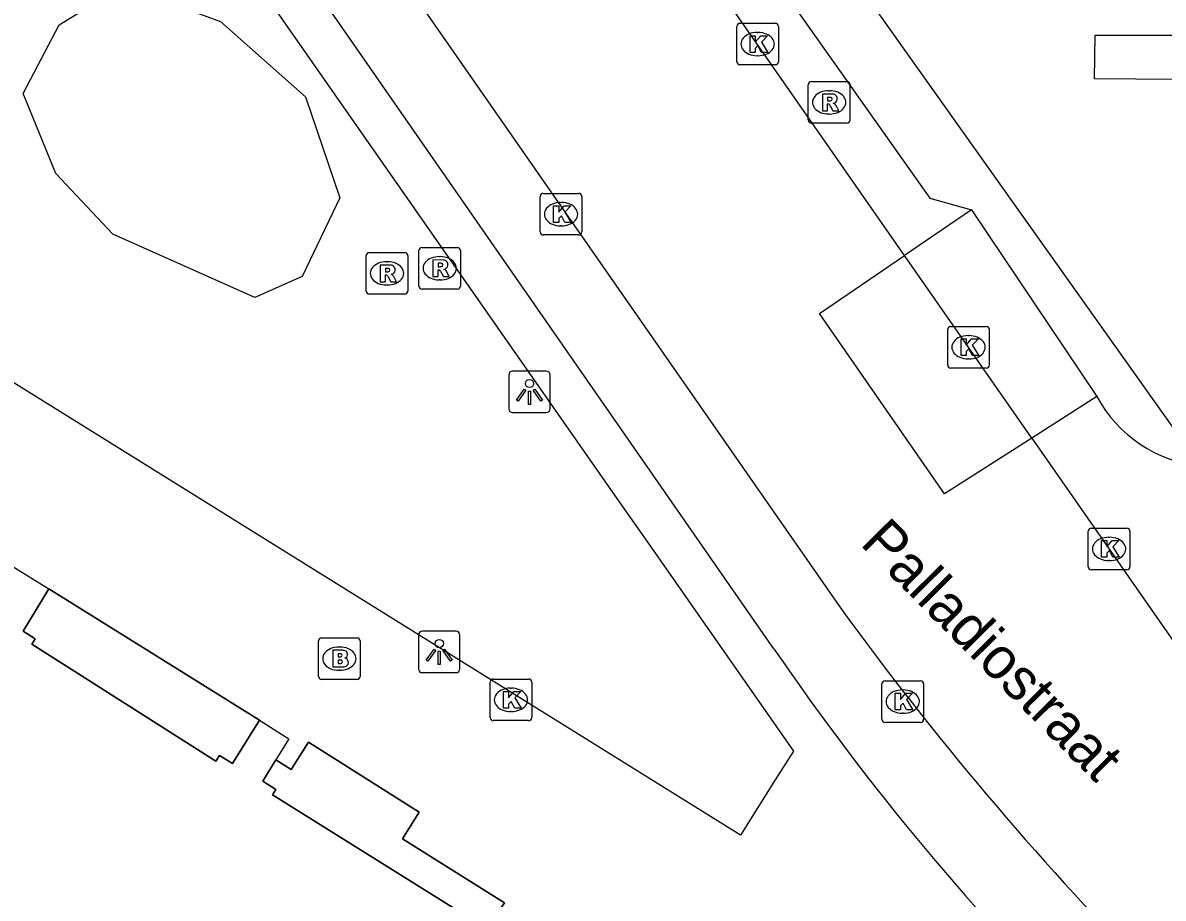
# Model space of a CAD drawing. Extents: x 159353 to 160616, y 385893 to 387321.
# Drawn here: x 159922.1 to 159949.51, y 386152.95 to 386173.99 of the extents above; entities that cross this region are included whole.
import ezdxf

# ---------------------------------------------------------------- set-up
doc = ezdxf.new("R2010")
doc.units = 0
for name, color, linetype in [('IMGEO_Brandkraan', 7, 'Continuous'), ('IMGEO_Groenvoorziening', 7, 'Continuous'), ('IMGEO_Kolk', 7, 'Continuous'), ('IMGEO_Lichtpunt', 7, 'Continuous'), ('IMGEO_Muur', 7, 'Continuous'), ('IMGEO_Openbare_ruimte_label', 7, 'Continuous'), ('IMGEO_Pand', 7, 'Continuous'), ('IMGEO_Pand_overbouw', 7, 'Continuous'), ('IMGEO_Rijbaan_lokaal_open', 7, 'Continuous'), ('IMGEO_Rioolput', 7, 'Continuous'), ('IMGEO_Voetpad_open', 7, 'Continuous')]:
    doc.layers.add(name, color=color, linetype=linetype)

msp = doc.modelspace()

# ---------------------------------------------------------------- linework, layer by layer
at = {"layer": 'IMGEO_Brandkraan'}
for p, q in [((159929.212, 386158.285), (159929.212, 386159.137)), ((159929.287, 386159.211), (159930.139, 386159.211)), ((159930.213, 386159.137), (159930.213, 386158.285)), ((159929.7, 386158.991), (159929.725, 386158.991)), ((159930.139, 386158.211), (159929.287, 386158.211)), ((159929.723, 386158.431), (159929.698, 386158.431))]:
    msp.add_line(p, q, dxfattribs=at)
for points in [[(159929.212, 386158.285), (159929.212, 386159.137)], [(159929.287, 386159.211), (159930.139, 386159.211)], [(159930.213, 386159.137), (159930.213, 386158.285)], [(159929.56, 386158.911), (159929.56, 386158.511), (159929.773, 386158.511)], [(159929.791, 386158.911), (159929.56, 386158.911)], [(159929.739, 386158.83), (159929.685, 386158.83), (159929.685, 386158.754)], [(159929.685, 386158.754), (159929.738, 386158.754)], [(159929.747, 386158.678), (159929.685, 386158.678), (159929.685, 386158.597)], [(159929.685, 386158.597), (159929.747, 386158.597)], [(159930.139, 386158.211), (159929.287, 386158.211)]]:
    msp.add_lwpolyline(points, dxfattribs=at)
for centre, radius, start, end in [((159929.289, 386159.135), 0.0765, 91.552, 178.448), ((159929.289, 386159.135), 0.0765, 91.552, 178.448), ((159930.137, 386159.135), 0.0765, 1.552, 88.448), ((159930.137, 386159.135), 0.0765, 1.552, 88.448), ((159929.74, 386158.792), 0.0379, 267.8285, 90.9355), ((159929.795, 386158.766), 0.145, 59.4692, 91.5367), ((159929.82, 386158.813), 0.0922, 285.5137, 58.1501), ((159929.748, 386158.637), 0.0404, 269.8759, 90.5077), ((159929.779, 386158.762), 0.251, 268.6676, 293.5347), ((159929.825, 386158.621), 0.105, 301.3115, 78.989), ((159929.289, 386158.287), 0.0765, 181.552, 268.448), ((159929.289, 386158.287), 0.0765, 181.552, 268.448), ((159930.137, 386158.287), 0.0765, 271.552, 358.448), ((159930.137, 386158.287), 0.0765, 271.552, 358.448)]:
    msp.add_arc(centre, radius, start, end, dxfattribs=at)
for centre, major_axis, ratio, start_param, end_param in [((159929.699, 386158.711), (-0.387, 0.002), 0.722429, 4.712389, 7.853982), ((159929.724, 386158.711), (-0.39, 0.002), 0.717154, 1.570796, 4.712389)]:
    msp.add_ellipse(centre, major_axis=major_axis, ratio=ratio, start_param=start_param, end_param=end_param, dxfattribs=at)
at = {"layer": 'IMGEO_Groenvoorziening'}
msp.add_lwpolyline([(159927.684, 386167.388), (159924.272, 386168.908), (159922.898, 386170.37), (159922.113, 386172.293), (159922.976, 386173.942), (159924.506, 386174.884), (159926.86, 386174.02), (159928.9, 386172.215), (159929.724, 386169.782), (159928.821, 386167.898), (159927.684, 386167.388)], dxfattribs=at)
at = {"layer": 'IMGEO_Kolk'}
for p, q in [((159939.265, 386173.054), (159939.265, 386173.906)), ((159939.34, 386173.98), (159940.192, 386173.98)), ((159940.266, 386173.906), (159940.266, 386173.054)), ((159939.753, 386173.76), (159939.778, 386173.76)), ((159940.192, 386172.98), (159939.34, 386172.98)), ((159939.776, 386173.2), (159939.751, 386173.2)), ((159934.54, 386168.966), (159934.54, 386169.818)), ((159934.615, 386169.892), (159935.467, 386169.892)), ((159935.541, 386169.818), (159935.541, 386168.966)), ((159935.028, 386169.672), (159935.053, 386169.672)), ((159935.467, 386168.892), (159934.615, 386168.892)), ((159935.051, 386169.112), (159935.026, 386169.112)), ((159944.408, 386166.694), (159945.26, 386166.694)), ((159944.333, 386165.768), (159944.333, 386166.62)), ((159944.821, 386166.474), (159944.846, 386166.474)), ((159945.334, 386166.62), (159945.334, 386165.768)), ((159944.844, 386165.914), (159944.819, 386165.914)), ((159945.26, 386165.694), (159944.408, 386165.694)), ((159947.712, 386160.921), (159947.712, 386161.773)), ((159947.787, 386161.847), (159948.639, 386161.847)), ((159948.713, 386161.773), (159948.713, 386160.921)), ((159948.2, 386161.627), (159948.225, 386161.627)), ((159948.223, 386161.067), (159948.198, 386161.067)), ((159948.639, 386160.847), (159947.787, 386160.847)), ((159933.41, 386158.221), (159934.262, 386158.221)), ((159942.828, 386158.179), (159943.68, 386158.179)), ((159933.335, 386157.295), (159933.335, 386158.147)), ((159933.823, 386158.001), (159933.848, 386158.001)), ((159934.336, 386158.147), (159934.336, 386157.295)), ((159942.753, 386157.253), (159942.753, 386158.105)), ((159943.241, 386157.959), (159943.266, 386157.959)), ((159943.754, 386158.105), (159943.754, 386157.253)), ((159933.846, 386157.441), (159933.821, 386157.441)), ((159943.264, 386157.399), (159943.239, 386157.399)), ((159934.262, 386157.221), (159933.41, 386157.221)), ((159943.68, 386157.179), (159942.828, 386157.179))]:
    msp.add_line(p, q, dxfattribs=at)
for points in [[(159939.265, 386173.054), (159939.265, 386173.906)], [(159939.34, 386173.98), (159940.192, 386173.98)], [(159940.266, 386173.906), (159940.266, 386173.054)], [(159939.586, 386173.68), (159939.709, 386173.68), (159939.709, 386173.529), (159939.839, 386173.68), (159940.003, 386173.68), (159939.857, 386173.529), (159940.01, 386173.28), (159939.858, 386173.28), (159939.773, 386173.444), (159939.709, 386173.377), (159939.709, 386173.28), (159939.586, 386173.28), (159939.586, 386173.68)], [(159940.192, 386172.98), (159939.34, 386172.98)], [(159934.54, 386168.966), (159934.54, 386169.818)], [(159934.615, 386169.892), (159935.467, 386169.892)], [(159935.541, 386169.818), (159935.541, 386168.966)], [(159934.861, 386169.592), (159934.984, 386169.592), (159934.984, 386169.441), (159935.114, 386169.592), (159935.278, 386169.592), (159935.132, 386169.441), (159935.285, 386169.192), (159935.133, 386169.192), (159935.048, 386169.356), (159934.984, 386169.289), (159934.984, 386169.192), (159934.861, 386169.192), (159934.861, 386169.592)], [(159935.467, 386168.892), (159934.615, 386168.892)], [(159944.408, 386166.694), (159945.26, 386166.694)], [(159944.333, 386165.768), (159944.333, 386166.62)], [(159945.334, 386166.62), (159945.334, 386165.768)], [(159944.654, 386166.394), (159944.777, 386166.394), (159944.777, 386166.243), (159944.907, 386166.394), (159945.071, 386166.394), (159944.925, 386166.243), (159945.078, 386165.994), (159944.926, 386165.994), (159944.841, 386166.158), (159944.777, 386166.091), (159944.777, 386165.994), (159944.654, 386165.994), (159944.654, 386166.394)], [(159945.26, 386165.694), (159944.408, 386165.694)], [(159947.712, 386160.921), (159947.712, 386161.773)], [(159947.787, 386161.847), (159948.639, 386161.847)], [(159948.713, 386161.773), (159948.713, 386160.921)], [(159948.033, 386161.547), (159948.156, 386161.547), (159948.156, 386161.396), (159948.286, 386161.547), (159948.45, 386161.547), (159948.304, 386161.396), (159948.457, 386161.147), (159948.305, 386161.147), (159948.22, 386161.311), (159948.156, 386161.244), (159948.156, 386161.147), (159948.033, 386161.147), (159948.033, 386161.547)], [(159948.639, 386160.847), (159947.787, 386160.847)], [(159933.41, 386158.221), (159934.262, 386158.221)], [(159942.828, 386158.179), (159943.68, 386158.179)], [(159933.335, 386157.295), (159933.335, 386158.147)], [(159933.656, 386157.921), (159933.779, 386157.921), (159933.779, 386157.77), (159933.909, 386157.921), (159934.073, 386157.921), (159933.927, 386157.77), (159934.08, 386157.521), (159933.928, 386157.521), (159933.843, 386157.685), (159933.779, 386157.618), (159933.779, 386157.521), (159933.656, 386157.521), (159933.656, 386157.921)], [(159934.336, 386158.147), (159934.336, 386157.295)], [(159942.753, 386157.253), (159942.753, 386158.105)], [(159943.754, 386158.105), (159943.754, 386157.253)], [(159943.074, 386157.879), (159943.197, 386157.879), (159943.197, 386157.728), (159943.327, 386157.879), (159943.491, 386157.879), (159943.345, 386157.728), (159943.498, 386157.479), (159943.346, 386157.479), (159943.261, 386157.643), (159943.197, 386157.576), (159943.197, 386157.479), (159943.074, 386157.479), (159943.074, 386157.879)], [(159934.262, 386157.221), (159933.41, 386157.221)], [(159943.68, 386157.179), (159942.828, 386157.179)]]:
    msp.add_lwpolyline(points, dxfattribs=at)
for centre, start, end in [((159939.342, 386173.904), 91.552, 178.448), ((159939.342, 386173.904), 91.552, 178.448), ((159940.19, 386173.904), 1.552, 88.448), ((159940.19, 386173.904), 1.552, 88.448), ((159939.342, 386173.056), 181.552, 268.448), ((159939.342, 386173.056), 181.552, 268.448), ((159940.19, 386173.056), 271.552, 358.448), ((159940.19, 386173.056), 271.552, 358.448), ((159934.617, 386169.816), 91.552, 178.448), ((159934.617, 386169.816), 91.552, 178.448), ((159935.465, 386169.816), 1.552, 88.448), ((159935.465, 386169.816), 1.552, 88.448), ((159934.617, 386168.968), 181.552, 268.448), ((159934.617, 386168.968), 181.552, 268.448), ((159935.465, 386168.968), 271.552, 358.448), ((159935.465, 386168.968), 271.552, 358.448), ((159944.41, 386166.618), 91.552, 178.448), ((159944.41, 386166.618), 91.552, 178.448), ((159945.258, 386166.618), 1.552, 88.448), ((159945.258, 386166.618), 1.552, 88.448), ((159944.41, 386165.77), 181.552, 268.448), ((159944.41, 386165.77), 181.552, 268.448), ((159945.258, 386165.77), 271.552, 358.448), ((159945.258, 386165.77), 271.552, 358.448), ((159947.789, 386161.771), 91.552, 178.448), ((159947.789, 386161.771), 91.552, 178.448), ((159948.637, 386161.771), 1.552, 88.448), ((159948.637, 386161.771), 1.552, 88.448), ((159947.789, 386160.923), 181.552, 268.448), ((159947.789, 386160.923), 181.552, 268.448), ((159948.637, 386160.923), 271.552, 358.448), ((159948.637, 386160.923), 271.552, 358.448), ((159933.412, 386158.145), 91.552, 178.448), ((159933.412, 386158.145), 91.552, 178.448), ((159934.26, 386158.145), 1.552, 88.448), ((159934.26, 386158.145), 1.552, 88.448), ((159942.83, 386158.103), 91.552, 178.448), ((159942.83, 386158.103), 91.552, 178.448), ((159943.678, 386158.103), 1.552, 88.448), ((159943.678, 386158.103), 1.552, 88.448), ((159933.412, 386157.297), 181.552, 268.448), ((159933.412, 386157.297), 181.552, 268.448), ((159934.26, 386157.297), 271.552, 358.448), ((159934.26, 386157.297), 271.552, 358.448), ((159942.83, 386157.255), 181.552, 268.448), ((159942.83, 386157.255), 181.552, 268.448), ((159943.678, 386157.255), 271.552, 358.448), ((159943.678, 386157.255), 271.552, 358.448)]:
    msp.add_arc(centre, 0.0765, start, end, dxfattribs=at)
for centre, major_axis, ratio, start_param, end_param in [((159939.752, 386173.48), (-0.387, 0.002), 0.722429, 4.712389, 7.853982), ((159939.777, 386173.48), (-0.39, 0.002), 0.717154, 1.570796, 4.712389), ((159935.027, 386169.392), (-0.387, 0.002), 0.722429, 4.712389, 7.853982), ((159935.052, 386169.392), (-0.39, 0.002), 0.717154, 1.570796, 4.712389), ((159944.82, 386166.194), (-0.387, 0.002), 0.722429, 4.712389, 7.853982), ((159944.845, 386166.194), (-0.39, 0.002), 0.717154, 1.570796, 4.712389), ((159948.199, 386161.347), (-0.387, 0.002), 0.722429, 4.712389, 7.853982), ((159948.224, 386161.347), (-0.39, 0.002), 0.717154, 1.570796, 4.712389), ((159933.822, 386157.721), (-0.387, 0.002), 0.722429, 4.712389, 7.853982), ((159933.847, 386157.721), (-0.39, 0.002), 0.717154, 1.570796, 4.712389), ((159943.24, 386157.679), (-0.387, 0.002), 0.722429, 4.712389, 7.853982), ((159943.265, 386157.679), (-0.39, 0.002), 0.717154, 1.570796, 4.712389)]:
    msp.add_ellipse(centre, major_axis=major_axis, ratio=ratio, start_param=start_param, end_param=end_param, dxfattribs=at)
at = {"layer": 'IMGEO_Lichtpunt'}
for p, q in [((159934.686, 386165.62), (159933.878, 386165.62)), ((159934.686, 386165.62), (159933.878, 386165.62)), ((159933.784, 386165.525), (159933.784, 386164.718)), ((159933.784, 386165.525), (159933.784, 386164.718)), ((159934.78, 386164.718), (159934.78, 386165.525)), ((159934.78, 386164.718), (159934.78, 386165.525)), ((159933.878, 386164.624), (159934.686, 386164.624)), ((159933.878, 386164.624), (159934.686, 386164.624)), ((159931.615, 386159.276), (159931.615, 386158.469)), ((159931.615, 386159.276), (159931.615, 386158.469)), ((159932.517, 386159.371), (159931.709, 386159.371)), ((159932.517, 386159.371), (159931.709, 386159.371)), ((159932.611, 386158.469), (159932.611, 386159.276)), ((159932.611, 386158.469), (159932.611, 386159.276)), ((159931.709, 386158.375), (159932.517, 386158.375)), ((159931.709, 386158.375), (159932.517, 386158.375))]:
    msp.add_line(p, q, dxfattribs=at)
for points in [[(159934.158, 386165.189), (159934.197, 386165.161), (159934.009, 386164.899), (159933.971, 386164.926), (159934.158, 386165.189)], [(159934.26, 386165.141), (159934.307, 386165.141), (159934.307, 386164.819), (159934.26, 386164.819), (159934.26, 386165.141)], [(159934.37, 386165.161), (159934.408, 386165.188), (159934.595, 386164.926), (159934.556, 386164.898), (159934.37, 386165.161)], [(159931.989, 386158.94), (159932.028, 386158.912), (159931.84, 386158.65), (159931.802, 386158.677), (159931.989, 386158.94)], [(159932.091, 386158.892), (159932.138, 386158.892), (159932.138, 386158.57), (159932.091, 386158.57), (159932.091, 386158.892)], [(159932.201, 386158.912), (159932.239, 386158.939), (159932.426, 386158.677), (159932.387, 386158.649), (159932.201, 386158.912)]]:
    msp.add_lwpolyline(points, dxfattribs=at)
for centre in [(159934.283, 386165.323), (159932.114, 386159.074)]:
    msp.add_circle(centre, 0.0994, dxfattribs=at)
for centre, start, end in [((159933.878, 386165.525), 90, 180), ((159933.878, 386165.525), 90, 180), ((159934.686, 386165.525), 0, 90), ((159934.686, 386165.525), 0, 90), ((159933.878, 386164.718), 180, 270), ((159933.878, 386164.718), 180, 270), ((159934.686, 386164.718), 270, 0), ((159934.686, 386164.718), 270, 360), ((159931.709, 386159.276), 90, 180), ((159931.709, 386159.276), 90, 180), ((159932.517, 386159.276), 0, 90), ((159932.517, 386159.276), 0, 90), ((159931.709, 386158.469), 180, 270), ((159931.709, 386158.469), 180, 270), ((159932.517, 386158.469), 270, 0), ((159932.517, 386158.469), 270, 360)]:
    msp.add_arc(centre, 0.0946, start, end, dxfattribs=at)
at = {"layer": 'IMGEO_Muur'}
msp.add_lwpolyline([(159952.828, 386172.605), (159947.863, 386172.645), (159947.875, 386173.695), (159952.802, 386173.696), (159952.828, 386172.605)], dxfattribs=at)
at = {"layer": 'IMGEO_Pand'}
for points in [[(159916.885, 386153.064), (159921.823, 386160.953), (159922.729, 386160.385)], [(159927.792, 386157.236), (159927.145, 386156.194), (159926.834, 386156.387), (159926.746, 386156.251), (159922.32, 386159.055), (159922.403, 386159.191), (159922.112, 386159.368), (159922.729, 386160.385)], [(159927.792, 386157.236), (159928.5, 386156.783), (159928.183, 386156.277)], [(159933.682, 386152.845), (159933.344, 386152.351), (159932.942, 386152.602), (159932.851, 386152.471), (159928.106, 386155.436), (159928.184, 386155.567), (159927.87, 386155.768), (159928.183, 386156.277)]]:
    msp.add_lwpolyline(points, dxfattribs=at)
at = {"layer": 'IMGEO_Pand_overbouw'}
for points in [[(159927.792, 386157.236), (159922.729, 386160.385), (159922.112, 386159.368), (159922.403, 386159.191), (159922.32, 386159.055), (159926.746, 386156.251), (159926.834, 386156.387), (159927.145, 386156.194)], [(159931.631, 386155.022), (159928.971, 386156.705), (159928.555, 386156.044), (159928.183, 386156.277), (159927.87, 386155.768), (159928.184, 386155.567), (159928.106, 386155.436), (159932.851, 386152.471), (159932.942, 386152.602), (159933.344, 386152.351), (159933.682, 386152.845), (159931.229, 386154.378)]]:
    msp.add_lwpolyline(points, close=True, dxfattribs=at)
at = {"layer": 'IMGEO_Rijbaan_lokaal_open'}
for points in [[(159950.418, 386163.332), (159935.64, 386184.131)], [(159934.663, 386182.851), (159943.907, 386169.776), (159944.906, 386169.496)], [(159925.909, 386182.701), (159941.775, 386159.906)], [(159943.298, 386168.4), (159933.698, 386182.179)], [(159944.906, 386169.496), (159947.92, 386165.009)], [(159946.357, 386164.01), (159944.26, 386162.67), (159941.249, 386167.002), (159943.298, 386168.4)], [(159946.357, 386164.01), (159950.025, 386158.745)]]:
    msp.add_lwpolyline(points, dxfattribs=at)
for centre, radius, start, end in [((159950.774, 386166.561), 3.249, 208.5402, 263.7099), ((160004.269, 386205.287), 77.233, 215.98595, 224.40306)]:
    msp.add_arc(centre, radius, start, end, dxfattribs=at)
at = {"layer": 'IMGEO_Rioolput'}
for p, q in [((159940.984, 386171.653), (159940.984, 386172.505)), ((159941.059, 386172.579), (159941.911, 386172.579)), ((159941.985, 386172.505), (159941.985, 386171.653)), ((159941.472, 386172.359), (159941.497, 386172.359)), ((159941.495, 386171.799), (159941.47, 386171.799)), ((159941.911, 386171.579), (159941.059, 386171.579)), ((159931.7, 386168.592), (159932.552, 386168.592)), ((159930.357, 386167.544), (159930.357, 386168.396)), ((159930.432, 386168.47), (159931.284, 386168.47)), ((159931.358, 386168.396), (159931.358, 386167.544)), ((159931.625, 386167.666), (159931.625, 386168.518)), ((159932.113, 386168.372), (159932.138, 386168.372)), ((159932.626, 386168.518), (159932.626, 386167.666)), ((159930.845, 386168.25), (159930.87, 386168.25)), ((159932.136, 386167.812), (159932.111, 386167.812)), ((159930.868, 386167.69), (159930.843, 386167.69)), ((159932.552, 386167.592), (159931.7, 386167.592)), ((159931.284, 386167.47), (159930.432, 386167.47))]:
    msp.add_line(p, q, dxfattribs=at)
for points in [[(159940.984, 386171.653), (159940.984, 386172.505)], [(159941.059, 386172.579), (159941.911, 386172.579)], [(159941.985, 386172.505), (159941.985, 386171.653)], [(159941.573, 386172.277), (159941.321, 386172.279), (159941.321, 386171.879)], [(159941.499, 386172.198), (159941.445, 386172.198), (159941.445, 386172.117)], [(159941.321, 386171.879), (159941.445, 386171.879), (159941.445, 386172.041), (159941.456, 386172.041)], [(159941.445, 386172.117), (159941.497, 386172.117)], [(159941.503, 386172.012), (159941.574, 386171.879), (159941.714, 386171.879), (159941.649, 386172.005)], [(159941.911, 386171.579), (159941.059, 386171.579)], [(159931.7, 386168.592), (159932.552, 386168.592)], [(159930.357, 386167.544), (159930.357, 386168.396)], [(159930.432, 386168.47), (159931.284, 386168.47)], [(159931.358, 386168.396), (159931.358, 386167.544)], [(159931.625, 386167.666), (159931.625, 386168.518)], [(159932.626, 386168.518), (159932.626, 386167.666)], [(159930.946, 386168.168), (159930.694, 386168.17), (159930.694, 386167.77)], [(159930.872, 386168.089), (159930.818, 386168.089), (159930.818, 386168.008)], [(159932.214, 386168.29), (159931.962, 386168.292), (159931.962, 386167.892)], [(159931.962, 386167.892), (159932.086, 386167.892), (159932.086, 386168.054), (159932.097, 386168.054)], [(159932.14, 386168.211), (159932.086, 386168.211), (159932.086, 386168.13)], [(159932.086, 386168.13), (159932.138, 386168.13)], [(159930.694, 386167.77), (159930.818, 386167.77), (159930.818, 386167.932), (159930.829, 386167.932)], [(159930.818, 386168.008), (159930.87, 386168.008)], [(159930.876, 386167.903), (159930.947, 386167.77), (159931.087, 386167.77), (159931.022, 386167.896)], [(159932.144, 386168.025), (159932.215, 386167.892), (159932.355, 386167.892), (159932.29, 386168.018)], [(159932.552, 386167.592), (159931.7, 386167.592)], [(159931.284, 386167.47), (159930.432, 386167.47)]]:
    msp.add_lwpolyline(points, dxfattribs=at)
for centre, radius, start, end in [((159941.061, 386172.503), 0.0765, 91.552, 178.448), ((159941.061, 386172.503), 0.0765, 91.552, 178.448), ((159941.909, 386172.503), 0.0765, 1.552, 88.448), ((159941.909, 386172.503), 0.0765, 1.552, 88.448), ((159941.505, 386172.102), 0.0964, 77.0061, 93.1865), ((159941.519, 386172.159), 0.0378, 276.6634, 79.6772), ((159941.572, 386172.167), 0.109, 350.3612, 89.416), ((159941.455, 386171.988), 0.0533, 26.0293, 88.6989), ((159941.481, 386172.306), 0.19, 274.7715, 282.9687), ((159941.57, 386172.167), 0.112, 277.5842, 350.9817), ((159941.554, 386171.952), 0.108, 29.5134, 73.7905), ((159941.061, 386171.655), 0.0765, 181.552, 268.448), ((159941.061, 386171.655), 0.0765, 181.552, 268.448), ((159941.909, 386171.655), 0.0765, 271.552, 358.448), ((159941.909, 386171.655), 0.0765, 271.552, 358.448), ((159931.702, 386168.516), 0.0765, 91.552, 178.448), ((159931.702, 386168.516), 0.0765, 91.552, 178.448), ((159932.55, 386168.516), 0.0765, 1.552, 88.448), ((159932.55, 386168.516), 0.0765, 1.552, 88.448), ((159930.434, 386168.394), 0.0765, 91.552, 178.448), ((159930.434, 386168.394), 0.0765, 91.552, 178.448), ((159931.282, 386168.394), 0.0765, 1.552, 88.448), ((159931.282, 386168.394), 0.0765, 1.552, 88.448), ((159930.878, 386167.993), 0.0964, 77.0061, 93.1865), ((159930.892, 386168.05), 0.0378, 276.6634, 79.6772), ((159930.945, 386168.058), 0.109, 350.3612, 89.416), ((159932.096, 386168.001), 0.0533, 26.0293, 88.6989), ((159932.122, 386168.319), 0.19, 274.7715, 282.9687), ((159932.146, 386168.115), 0.0964, 77.0061, 93.1865), ((159932.16, 386168.172), 0.0378, 276.6634, 79.6772), ((159932.213, 386168.18), 0.109, 350.3612, 89.416), ((159932.211, 386168.18), 0.112, 277.5842, 350.9817), ((159932.195, 386167.965), 0.108, 29.5134, 73.7905), ((159930.828, 386167.879), 0.0533, 26.0293, 88.6989), ((159930.854, 386168.197), 0.19, 274.7715, 282.9687), ((159930.943, 386168.058), 0.112, 277.5842, 350.9817), ((159930.927, 386167.843), 0.108, 29.5134, 73.7905), ((159930.434, 386167.546), 0.0765, 181.552, 268.448), ((159930.434, 386167.546), 0.0765, 181.552, 268.448), ((159931.282, 386167.546), 0.0765, 271.552, 358.448), ((159931.282, 386167.546), 0.0765, 271.552, 358.448), ((159931.702, 386167.668), 0.0765, 181.552, 268.448), ((159931.702, 386167.668), 0.0765, 181.552, 268.448), ((159932.55, 386167.668), 0.0765, 271.552, 358.448), ((159932.55, 386167.668), 0.0765, 271.552, 358.448)]:
    msp.add_arc(centre, radius, start, end, dxfattribs=at)
for centre, major_axis, ratio, start_param, end_param in [((159941.471, 386172.079), (-0.387, 0.002), 0.722429, 4.712389, 7.853982), ((159941.496, 386172.079), (-0.39, 0.002), 0.717154, 1.570796, 4.712389), ((159932.112, 386168.092), (-0.387, 0.002), 0.722429, 4.712389, 7.853982), ((159932.137, 386168.092), (-0.39, 0.002), 0.717154, 1.570796, 4.712389), ((159930.844, 386167.97), (-0.387, 0.002), 0.722429, 4.712389, 7.853982), ((159930.869, 386167.97), (-0.39, 0.002), 0.717154, 1.570796, 4.712389)]:
    msp.add_ellipse(centre, major_axis=major_axis, ratio=ratio, start_param=start_param, end_param=end_param, dxfattribs=at)
at = {"layer": 'IMGEO_Voetpad_open'}
for points in [[(159915.414, 386187.292), (159919.465, 386186.776), (159936.608, 386162.243), (159937.142, 386161.478), (159940.626, 386156.491), (159940.19, 386155.797), (159939.355, 386154.471), (159904.863, 386175.937)], [(159940.156, 386158.949), (159926.092, 386179.192)], [(159944.906, 386169.496), (159943.298, 386168.4)], [(159946.357, 386164.01), (159943.298, 386168.4)], [(159947.92, 386165.009), (159946.357, 386164.01)], [(159922.729, 386160.385), (159927.792, 386157.236)], [(159928.183, 386156.277), (159928.555, 386156.044), (159928.971, 386156.705), (159931.631, 386155.022), (159931.229, 386154.378), (159933.682, 386152.845)]]:
    msp.add_lwpolyline(points, dxfattribs=at)
msp.add_arc((159991.635, 386194.139), 62.357, 214.35565, 225.42624, dxfattribs=at)

# ---------------------------------------------------------------- texts
at = {"layer": 'IMGEO_Openbare_ruimte_label'}
msp.add_text('Palladiostraat', height=1, rotation=314.7569, dxfattribs=at).set_placement((159942.204, 386161.46))

doc.saveas('drawing.dxf')
